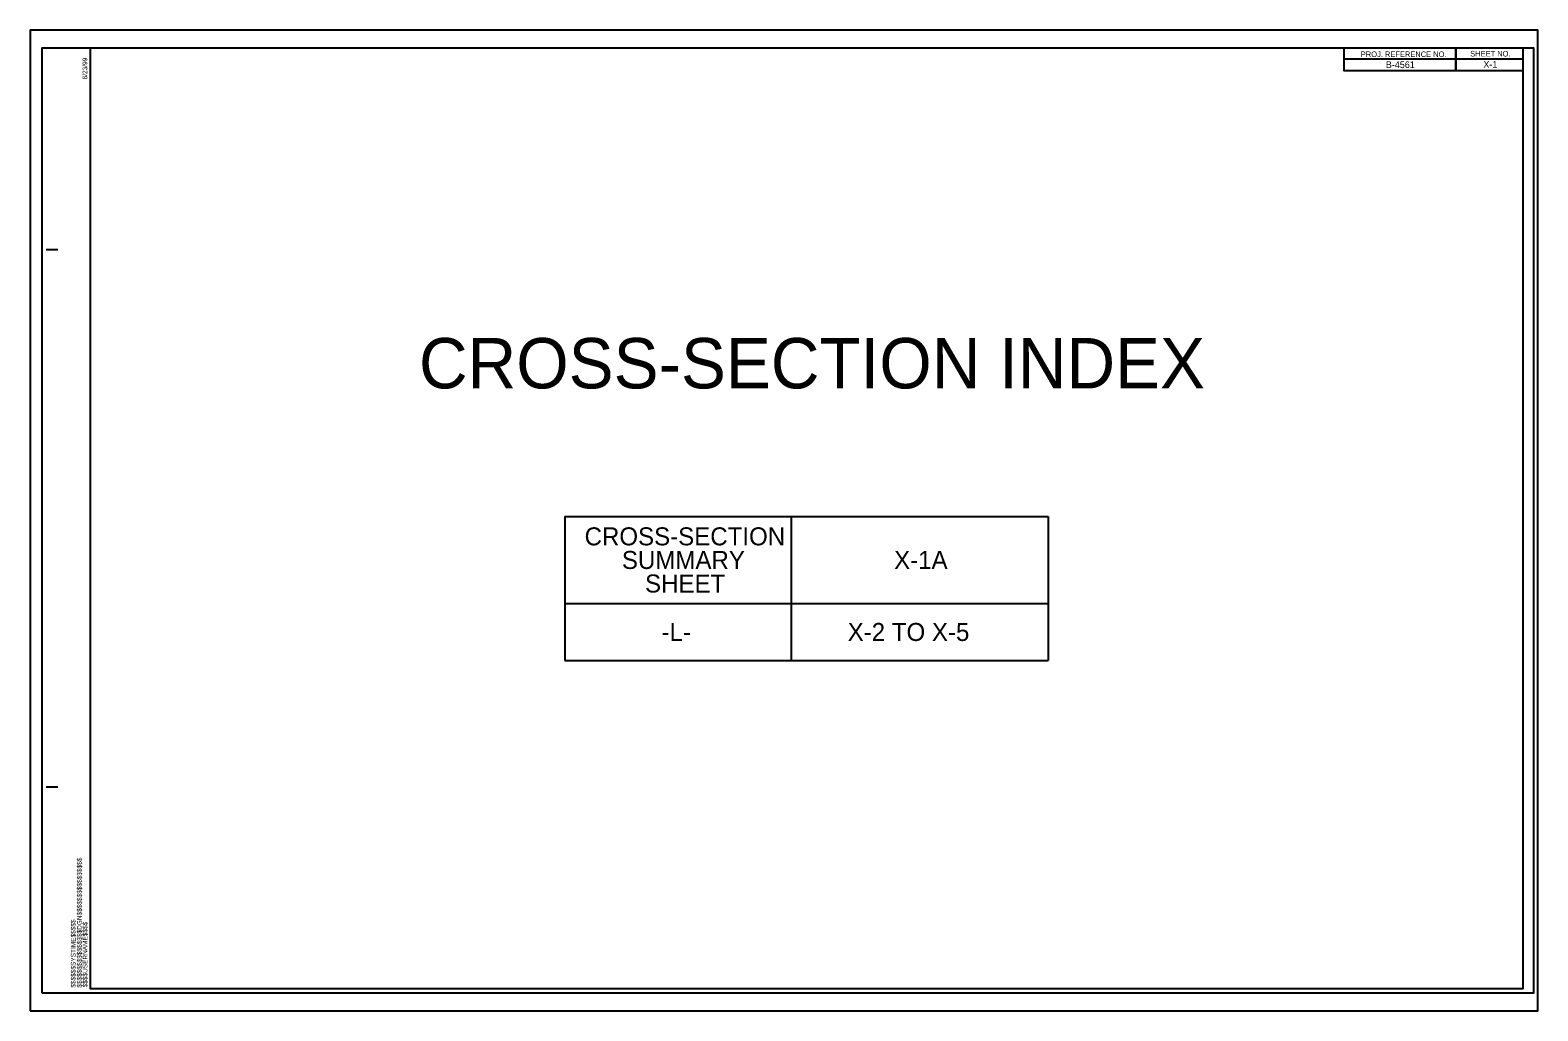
# Model space of a CAD drawing. Extents: x -13 to 323, y 1315 to 1534.
import ezdxf

# ---------------------------------------------------------------- set-up
doc = ezdxf.new("R2010")
doc.units = 0
for name, color, linetype in [('Prop Dimension', 7, 'Continuous'), ('Prop Dimension Text', 7, 'Continuous'), ('Sheet Cross Section CELL', 7, 'Continuous'), ('Sheet Cutting Line CELL', 7, 'Continuous'), ('Sheet Plot Border Inside CELL', 7, 'Continuous'), ('Sheet Plot Border Outside CELL', 7, 'Continuous')]:
    doc.layers.add(name, color=color, linetype=linetype)

msp = doc.modelspace()

# ---------------------------------------------------------------- linework, layer by layer
at = {"layer": 'Prop Dimension'}
for p, q in [((106.04, 1425.4), (106.04, 1393.23)), ((106.04, 1425.4), (213.96, 1425.4)), ((156.55, 1425.4), (156.55, 1393.23)), ((213.96, 1425.4), (213.96, 1393.23)), ((106.04, 1405.99), (213.96, 1405.99)), ((106.04, 1393.23), (213.96, 1393.23))]:
    msp.add_line(p, q, dxfattribs=at)
at = {"layer": 'Sheet Cross Section CELL'}
for p, q in [((305, 1530), (305, 1525)), ((305, 1525), (305, 1530)), ((280, 1527.5), (280, 1525)), ((320, 1527.49), (280, 1527.49)), ((280, 1525), (320, 1525)), ((-9.8, 1485), (-7.3, 1485)), ((-9.7, 1485), (-7.2, 1485)), ((-9.8, 1365), (-7.3, 1365)), ((-9.7, 1365), (-7.2, 1365)), ((0, 1320), (0, 1320)), ((0, 1320), (0, 1320)), ((0, 1320), (0, 1320)), ((0, 1320), (0, 1320)), ((0, 1320), (0, 1320)), ((0, 1320), (0, 1320)), ((0, 1320), (0, 1320))]:
    msp.add_line(p, q, dxfattribs=at)
for points in [[(320, 1530), (0, 1530), (0, 1320), (320, 1320)], [(320, 1530), (280, 1530), (280, 1525), (320, 1525)]]:
    msp.add_lwpolyline(points, close=True, dxfattribs=at)
at = {"layer": 'Sheet Cutting Line CELL'}
for p, q in [((323.3, 1534), (-13.4, 1534)), ((-13.4, 1534), (-13.4, 1315)), ((-13.4, 1315), (323.3, 1315))]:
    msp.add_line(p, q, dxfattribs=at)
at = {"layer": 'Sheet Plot Border Inside CELL'}
msp.add_lwpolyline([(-10.8, 1319), (322.4, 1319), (322.4, 1530), (-10.8, 1530)], close=True, dxfattribs=at)
at = {"layer": 'Sheet Plot Border Outside CELL'}
msp.add_lwpolyline([(-13.4, 1315), (323.3, 1315), (323.3, 1534), (-13.4, 1534)], close=True, dxfattribs=at)

# ---------------------------------------------------------------- texts
at = {"layer": 'Prop Dimension Text'}
for s, height, p in [('CROSS-SECTION INDEX', 11.25, (73.43, 1454)), ('CROSS-SECTION', 4.0186, (110.42, 1418.95)), ('SUMMARY', 4.019, (118.75, 1413.68)), ('X-1A', 4.019, (179.54, 1413.68)), ('SHEET', 4.019, (123.92, 1408.42)), ('-L-', 4.019, (127.6, 1397.6)), ('X-2 TO X-5', 4.019, (169.17, 1397.6))]:
    msp.add_text(s, height=height, dxfattribs=at).set_placement(p)
at = {"layer": 'Sheet Cross Section CELL'}
for s, height, p in [('PROJ. REFERENCE NO.', 1.25, (283.77, 1527.99)), ('SHEET NO.', 1.25, (308.19, 1528.12)), ('B-4561', 1.5, (289.35, 1525.53)), ('X-1', 1.5, (311.14, 1525.6))]:
    msp.add_text(s, height=height, dxfattribs=at).set_placement(p)
for s, p in [('8/23/99', (-0.65, 1523)), ('$$$$$$$$$$$$$$$$DGN$$$$$$$$$$$$$$$$', (-1.88, 1320.18)), ('$$$$$$SYSTIME$$$$$', (-3.26, 1320.18)), ('$$$$USERNAME$$$$', (-0.62, 1320.23))]:
    msp.add_text(s, height=1.05, rotation=90, dxfattribs=at).set_placement(p)

doc.saveas('drawing.dxf')
